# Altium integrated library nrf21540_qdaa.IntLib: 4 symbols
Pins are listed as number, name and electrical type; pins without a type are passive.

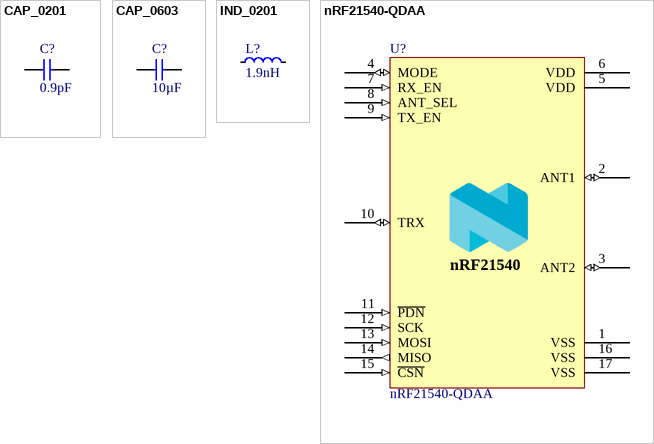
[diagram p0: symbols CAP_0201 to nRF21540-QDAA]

## CAP_0201
designator C?, comment 0.9pF
Capacitor, NP0, ±5%; Part Number: C0201-0.9p
footprint CAPC0603X03L_C
pins: 1, 2

## CAP_0603
designator C?, comment 10µF
Capacitor, X7S, ±20%; Part Number: C0603-10µ
footprint CAPC1608X06L
pins: 1, 2

## IND_0201
designator L?, comment 1.9nH
High frequency chip inductor ±5%; Part Number: L0201-1n9
footprint INDC0603X03L_C
pins: 1, 2

## nRF21540-QDAA
designator U?
Radio front-end / range extender for 2.4GHz
footprint QFN65P400X400X65_HS-17N
pins: 1 VSS (power), 2 ANT1 (io), 3 ANT2 (io), 4 MODE (io), 5 VDD (power), 6 VDD (power), 7 RX_EN (in), 8 ANT_SEL (in), 9 TX_EN (in), 10 TRX (io), 11 ~{PDN} (in), 12 SCK (in), 13 MOSI (in), 14 MISO (out), 15 ~{CSN} (in), 16 VSS (power), 17 VSS (power)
